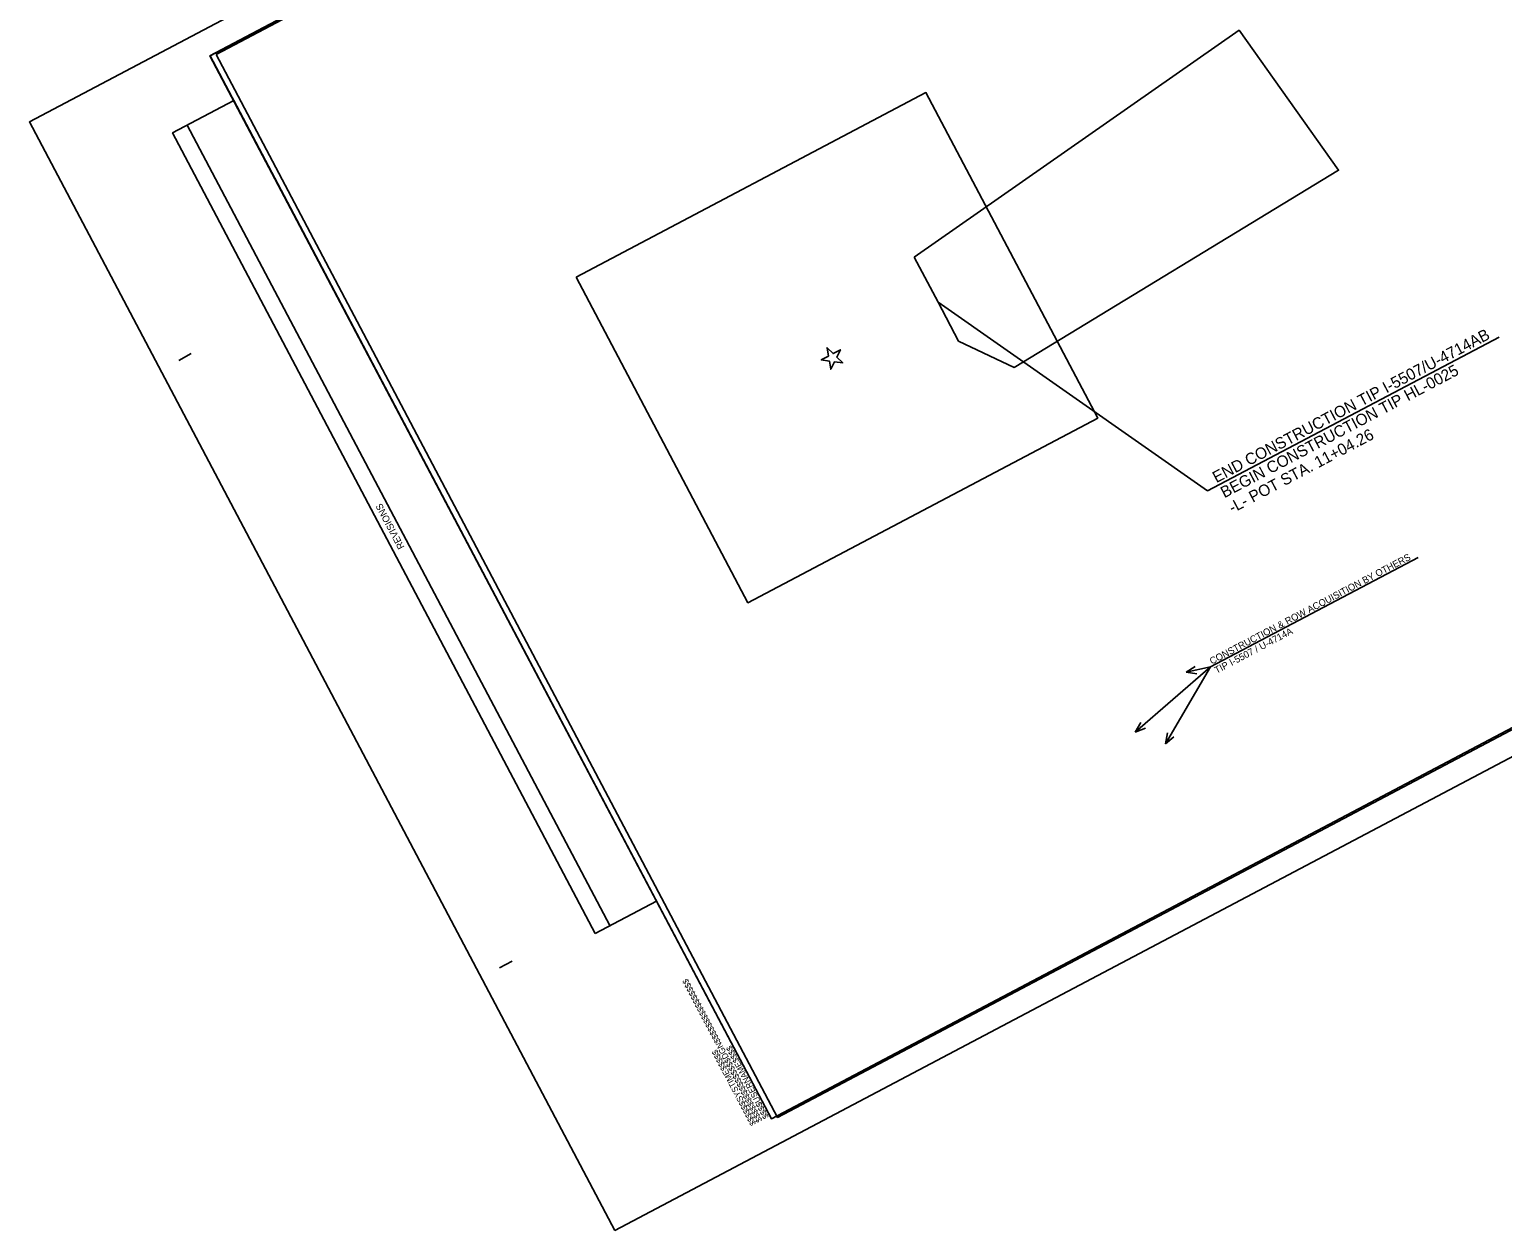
# Model space of a CAD drawing. Extents: x 1487051 to 1489241, y 497582 to 499399.
# Drawn here: x 1487051 to 1488337, y 497582 to 498631 of the extents above; entities that cross this region are included whole.
import ezdxf

# ---------------------------------------------------------------- set-up
doc = ezdxf.new("R2010")
doc.units = 0
for name, color, linetype in [('Exist DTM Regular Point CELL', 7, 'Continuous'), ('Exist DTM Regular Point Cogo Elevation', 7, 'Continuous'), ('Exist Other Culture Sign Post Cogo Comment', 7, 'Continuous'), ('Exist Other Culture Sign Post Cogo Elevation', 7, 'Continuous'), ('Exist Property Iron Pin Cogo Comment', 7, 'Continuous'), ('Exist Roads EOP Cogo Point CELL', 7, 'Continuous'), ('Exist Structure Minor Pipes RCP 15 Inch Cogo Comment', 7, 'Continuous'), ('Exist Structure Minor Pipes RCP 15 Inch Cogo Elevation', 7, 'Continuous')]:
    doc.layers.add(name, color=color, linetype=linetype)

msp = doc.modelspace()

# ---------------------------------------------------------------- linework, layer by layer
at = {"layer": 'Exist DTM Regular Point CELL'}
for p, q in [((1487844.4, 498392.9), (1488079.9, 498227.9)), ((1488079.9, 498227.9), (1488334.6, 498362.4)), ((1488082.4, 498074.2), (1488263.6, 498169.9)), ((1488069.1, 498074.7), (1488061, 498069.6)), ((1488082.4, 498074.2), (1488016.7, 498017.4)), ((1488082.4, 498074.2), (1488043.1, 498007.2)), ((1488082.4, 498074.2), (1488061, 498069.6)), ((1488070.5, 498068.3), (1488061, 498069.6)), ((1488021.4, 498025.7), (1488016.7, 498017.4)), ((1488025.7, 498020.8), (1488016.7, 498017.4)), ((1488044.9, 498016.6), (1488043.1, 498007.2)), ((1488050.5, 498013.3), (1488043.1, 498007.2))]:
    msp.add_line(p, q, dxfattribs=at)
at = {"layer": 'Exist DTM Regular Point Cogo Elevation'}
for points in [[(1487208.7, 498608.1), (1488222.1, 499143.2), (1488965.4, 498493.7), (1489025.4, 498380), (1487698.9, 497679.6)], [(1487208.7, 498608.1), (1488222.1, 499143.2), (1488965.4, 498493.7), (1489025.4, 498380), (1487698.9, 497679.6)], [(1487214, 498609.2), (1488227.4, 499144.3), (1488970.7, 498494.8), (1489030.7, 498381.1), (1487704.3, 497680.7)], [(1487823.6, 498432.2), (1487844.4, 498392.9), (1487862.4, 498358.9), (1487910.8, 498335.8), (1488194.2, 498508), (1488107.4, 498630.3)]]:
    msp.add_lwpolyline(points, close=True, dxfattribs=at)
at = {"layer": 'Exist Other Culture Sign Post Cogo Comment'}
msp.add_lwpolyline([(1488264.2, 499106.4), (1488223.1, 499143.8), (1487208.6, 498608.1), (1487698.9, 497679.6), (1489025.4, 498380), (1488872, 498670.6), (1488744.3, 498686.9)], close=True, dxfattribs=at)
at = {"layer": 'Exist Other Culture Sign Post Cogo Elevation'}
msp.add_lwpolyline([(1487748.8, 498345.8), (1487742.4, 498342.4), (1487749.6, 498341.4), (1487750.8, 498334.2), (1487754, 498340.7), (1487761.2, 498339.7), (1487756, 498344.8), (1487759.2, 498351.3), (1487752.8, 498347.9), (1487747.6, 498353), (1487748.8, 498345.8)], dxfattribs=at)
at = {"layer": 'Exist Property Iron Pin Cogo Comment'}
msp.add_lwpolyline([(1487528.3, 498414.6), (1487833.8, 498575.9), (1487983.9, 498291.6), (1487678.4, 498130.3)], close=True, dxfattribs=at)
at = {"layer": 'Exist Roads EOP Cogo Point CELL'}
msp.add_lwpolyline([(1487562.2, 497582), (1489050.9, 498368), (1488539.7, 499336.3), (1487050.9, 498550.3)], close=True, dxfattribs=at)
at = {"layer": 'Exist Structure Minor Pipes RCP 15 Inch Cogo Comment'}
for p, q in [((1487208.7, 498608.1), (1487208.7, 498608.1)), ((1487181.3, 498342), (1487192.3, 498347.9)), ((1487461.4, 497811.4), (1487472.5, 497817.3)), ((1487698.9, 497679.6), (1487698.9, 497679.6))]:
    msp.add_line(p, q, dxfattribs=at)
for points in [[(1488535.1, 499308.5), (1487208.7, 498608.1), (1487698.9, 497679.6), (1489025.4, 498380)], [(1487698.9, 497679.6), (1487208.7, 498608.1), (1488358.2, 499215.1), (1488375.7, 499181.9), (1488552.6, 499275.3), (1489025.4, 498380)]]:
    msp.add_lwpolyline(points, close=True, dxfattribs=at)
at = {"layer": 'Exist Structure Minor Pipes RCP 15 Inch Cogo Elevation'}
msp.add_line((1487557.9, 497848.3), (1487188.7, 498547.4), dxfattribs=at)
msp.add_lwpolyline([(1487545, 497841.5), (1487175.9, 498540.6), (1487229.4, 498568.9), (1487598.6, 497869.7)], close=True, dxfattribs=at)

# ---------------------------------------------------------------- texts
at = {"layer": 'Exist DTM Regular Point CELL'}
for s, height, p in [('END CONSTRUCTION TIP I-5507/U-4714AB', 10, (1488087.5, 498234.7)), ('BEGIN CONSTRUCTION TIP HL-0025', 10, (1488094.5, 498221.5)), ('-L- POT STA. 11+04.26', 10, (1488101.5, 498208.2)), ('CONSTRUCTION & ROW ACQUISITION BY OTHERS', 6, (1488083.6, 498076.2)), ('TIP I-5507 / U-4714A', 6, (1488087.8, 498068.2))]:
    msp.add_text(s, height=height, rotation=27.8351, dxfattribs=at).set_placement(p)
at = {"layer": 'Exist Structure Minor Pipes RCP 15 Inch Cogo Comment'}
for s, p in [('$$$$$$$$$$$$$$$$DGN$$$$$$$$$$$$$$$$', (1487691.1, 497678.1)), ('$$$$USERNAME$$$$', (1487696.9, 497681.2)), ('$$$$$$SYSTIME$$$$$', (1487685.7, 497675.3))]:
    msp.add_text(s, height=5.25, rotation=117.8351, dxfattribs=at).set_placement(p)
at = {"layer": 'Exist Structure Minor Pipes RCP 15 Inch Cogo Elevation'}
msp.add_text('REVISIONS', height=6, rotation=117.8351, dxfattribs=at).set_placement((1487378.7, 498179))

doc.saveas('drawing.dxf')
